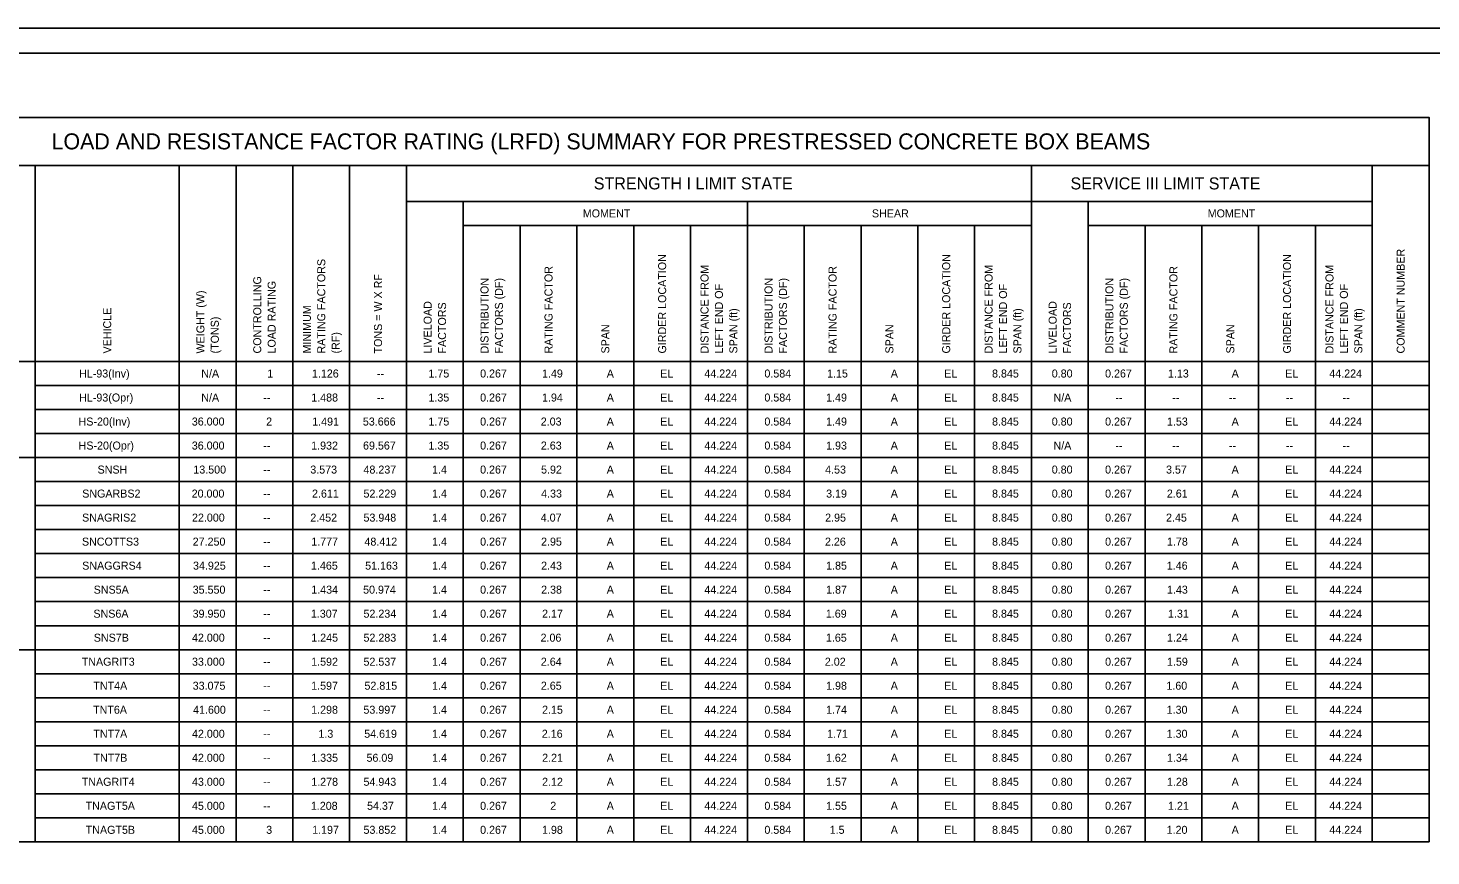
# Model space of a CAD drawing. Extents: x -169 to 381, y 285 to 620.
# Drawn here: x 28.2 to 247.3, y 375.4 to 504.7 of the extents above; entities that cross this region are included whole.
import ezdxf

# ---------------------------------------------------------------- set-up
doc = ezdxf.new("R2010")
doc.units = 0
for name, color, linetype in [('Bill of Material Border Lines', 7, 'Continuous'), ('Bill of Material Lines', 7, 'Continuous'), ('Miscellaneous Lines', 7, 'Continuous'), ('Plan Sheet CELL', 7, 'Continuous'), ('Plot Shape CELL', 7, 'Continuous'), ('Text', 7, 'Continuous')]:
    doc.layers.add(name, color=color, linetype=linetype)

msp = doc.modelspace()

# ---------------------------------------------------------------- linework, layer by layer
at = {"layer": 'Bill of Material Border Lines'}
msp.add_lwpolyline([(10.55, 490.71), (247.05, 490.71), (247.05, 377.59), (10.55, 377.59), (10.55, 490.71)], dxfattribs=at)
at = {"layer": 'Bill of Material Lines'}
for p, q in [((10.55, 483.21), (247.05, 483.21)), ((29.3, 483.21), (29.3, 377.59)), ((51.8, 483.21), (51.8, 377.59)), ((60.67, 483.21), (60.67, 377.59)), ((69.55, 483.21), (69.55, 377.59)), ((78.42, 483.21), (78.42, 377.59)), ((87.3, 483.21), (87.3, 377.59)), ((184.92, 483.21), (184.92, 377.59)), ((238.17, 483.21), (238.17, 377.59)), ((247.05, 483.21), (247.05, 377.59)), ((87.3, 477.59), (238.17, 477.59)), ((96.17, 477.59), (96.17, 377.59)), ((140.55, 477.59), (140.55, 377.59)), ((193.8, 477.59), (193.8, 377.59)), ((96.17, 473.84), (184.92, 473.84)), ((105.05, 473.84), (105.05, 377.59)), ((113.92, 473.84), (113.92, 377.59)), ((122.8, 473.84), (122.8, 377.59)), ((131.67, 473.84), (131.67, 377.59)), ((149.42, 473.84), (149.42, 377.59)), ((158.3, 473.84), (158.3, 377.59)), ((167.17, 473.84), (167.17, 377.59)), ((176.05, 473.84), (176.05, 377.59)), ((193.8, 473.84), (238.17, 473.84)), ((202.67, 473.84), (202.67, 377.59)), ((211.55, 473.84), (211.55, 377.59)), ((220.42, 473.84), (220.42, 377.59)), ((229.3, 473.84), (229.3, 377.59)), ((10.55, 452.59), (247.05, 452.59)), ((29.3, 448.84), (247.05, 448.84)), ((29.3, 445.09), (247.05, 445.09)), ((29.3, 441.34), (247.05, 441.34)), ((10.55, 437.59), (247.05, 437.59)), ((29.3, 433.84), (247.05, 433.84)), ((29.3, 430.09), (247.05, 430.09)), ((29.3, 426.34), (247.05, 426.34)), ((29.3, 422.59), (247.05, 422.59)), ((29.3, 418.84), (247.05, 418.84)), ((29.3, 415.09), (247.05, 415.09)), ((29.3, 411.34), (247.05, 411.34)), ((23.17, 407.59), (247.05, 407.59)), ((29.3, 403.84), (247.05, 403.84)), ((29.3, 400.09), (247.05, 400.09)), ((29.3, 396.34), (247.05, 396.34)), ((29.3, 392.59), (247.05, 392.59)), ((29.3, 388.84), (247.05, 388.84)), ((29.3, 385.09), (247.05, 385.09)), ((29.3, 381.34), (247.05, 381.34))]:
    msp.add_line(p, q, dxfattribs=at)
at = {"layer": 'Plan Sheet CELL'}
msp.add_line((3.77, 500.71), (323.78, 500.71), dxfattribs=at)
at = {"layer": 'Plot Shape CELL'}
msp.add_lwpolyline([(-6.77, 504.65), (323.86, 504.65), (323.86, 284.65), (-6.77, 284.65)], close=True, dxfattribs=at)

# ---------------------------------------------------------------- texts
at = {"layer": 'Miscellaneous Lines'}
for s, p in [('1', (65.54, 450.09)), ('1.13', (206.25, 450.09)), ('44.224', (231.46, 450.09)), ('2', (65.38, 442.59)), ('1.49', (152.85, 442.59)), ('8.845', (178.77, 442.59)), ('3', (65.38, 378.84)), ('1.20', (206.05, 378.84)), ('44.224', (231.46, 378.84))]:
    msp.add_text(s, height=1.25, dxfattribs=at).set_placement(p)
at = {"layer": 'Text'}
for s, height, p in [('LOAD AND RESISTANCE FACTOR RATING (LRFD) SUMMARY FOR PRESTRESSED CONCRETE BOX BEAMS', 2.5, (31.85, 485.71)), ('STRENGTH I LIMIT STATE', 1.875, (116.56, 479.46)), ('SERVICE III LIMIT STATE', 1.875, (191.03, 479.46)), ('MOMENT', 1.25, (114.84, 475.09)), ('SHEAR', 1.25, (160.01, 475.09)), ('MOMENT', 1.25, (212.46, 475.09)), ('HL-93(Inv)', 1.25, (36.15, 450.09)), ('N/A', 1.25, (55.24, 450.09)), ('1.126', 1.25, (72.53, 450.09)), ('--', 1.25, (82.67, 450.09)), ('1.75', 1.25, (90.73, 450.09)), ('0.267', 1.25, (98.8, 450.09)), ('1.49', 1.25, (108.47, 450.09)), ('A', 1.25, (118.58, 450.09)), ('EL', 1.25, (126.94, 450.09)), ('44.224', 1.25, (133.83, 450.09)), ('0.584', 1.25, (143.21, 450.09)), ('1.15', 1.25, (153, 450.09)), ('A', 1.25, (162.95, 450.09)), ('EL', 1.25, (171.31, 450.09)), ('8.845', 1.25, (178.77, 450.09)), ('0.80', 1.25, (188.1, 450.09)), ('0.267', 1.25, (196.43, 450.09)), ('A', 1.25, (216.2, 450.09)), ('EL', 1.25, (224.56, 450.09)), ('HL-93(Opr)', 1.25, (36.16, 446.34)), ('N/A', 1.25, (55.24, 446.34)), ('1.488', 1.25, (72.42, 446.34)), ('1.35', 1.25, (90.73, 446.34)), ('0.267', 1.25, (98.8, 446.34)), ('1.94', 1.25, (108.47, 446.34)), ('A', 1.25, (118.58, 446.34)), ('EL', 1.25, (126.94, 446.34)), ('44.224', 1.25, (133.83, 446.34)), ('0.584', 1.25, (143.21, 446.34)), ('1.49', 1.25, (152.85, 446.34)), ('A', 1.25, (162.95, 446.34)), ('EL', 1.25, (171.31, 446.34)), ('8.845', 1.25, (178.77, 446.34)), ('N/A', 1.25, (188.37, 446.34)), ('--', 1.25, (64.92, 446.34)), ('--', 1.25, (82.67, 446.34)), ('--', 1.25, (198.04, 446.34)), ('--', 1.25, (206.92, 446.34)), ('--', 1.25, (215.79, 446.34)), ('--', 1.25, (224.67, 446.34)), ('--', 1.25, (233.54, 446.34)), ('HS-20(Inv)', 1.25, (36.07, 442.59)), ('36.000', 1.25, (53.76, 442.59)), ('1.491', 1.25, (72.57, 442.59)), ('53.666', 1.25, (80.48, 442.59)), ('1.75', 1.25, (90.73, 442.59)), ('0.267', 1.25, (98.8, 442.59)), ('2.03', 1.25, (108.27, 442.59)), ('A', 1.25, (118.58, 442.59)), ('EL', 1.25, (126.94, 442.59)), ('44.224', 1.25, (133.83, 442.59)), ('0.584', 1.25, (143.21, 442.59)), ('A', 1.25, (162.95, 442.59)), ('EL', 1.25, (171.31, 442.59)), ('0.80', 1.25, (188.1, 442.59)), ('0.267', 1.25, (196.43, 442.59)), ('1.53', 1.25, (206.1, 442.59)), ('A', 1.25, (216.2, 442.59)), ('EL', 1.25, (224.56, 442.59)), ('44.224', 1.25, (231.46, 442.59)), ('HS-20(Opr)', 1.25, (36.08, 438.84)), ('36.000', 1.25, (53.76, 438.84)), ('--', 1.25, (64.92, 438.84)), ('1.932', 1.25, (72.41, 438.84)), ('69.567', 1.25, (80.51, 438.84)), ('1.35', 1.25, (90.73, 438.84)), ('0.267', 1.25, (98.8, 438.84)), ('2.63', 1.25, (108.29, 438.84)), ('A', 1.25, (118.58, 438.84)), ('EL', 1.25, (126.94, 438.84)), ('44.224', 1.25, (133.83, 438.84)), ('0.584', 1.25, (143.21, 438.84)), ('1.93', 1.25, (152.85, 438.84)), ('A', 1.25, (162.95, 438.84)), ('EL', 1.25, (171.31, 438.84)), ('8.845', 1.25, (178.77, 438.84)), ('N/A', 1.25, (188.37, 438.84)), ('--', 1.25, (198.04, 438.84)), ('--', 1.25, (206.92, 438.84)), ('--', 1.25, (215.79, 438.84)), ('--', 1.25, (224.67, 438.84)), ('--', 1.25, (233.54, 438.84)), ('SNSH', 1.25, (39.04, 435.09)), ('13.500', 1.25, (54, 435.09)), ('3.573', 1.25, (72.27, 435.09)), ('48.237', 1.25, (80.58, 435.09)), ('1.4', 1.25, (91.29, 435.09)), ('0.267', 1.25, (98.8, 435.09)), ('5.92', 1.25, (108.32, 435.09)), ('A', 1.25, (118.58, 435.09)), ('EL', 1.25, (126.94, 435.09)), ('44.224', 1.25, (133.83, 435.09)), ('0.584', 1.25, (143.21, 435.09)), ('4.53', 1.25, (152.7, 435.09)), ('A', 1.25, (162.95, 435.09)), ('EL', 1.25, (171.31, 435.09)), ('8.845', 1.25, (178.77, 435.09)), ('0.80', 1.25, (188.1, 435.09)), ('0.267', 1.25, (196.43, 435.09)), ('3.57', 1.25, (205.95, 435.09)), ('A', 1.25, (216.2, 435.09)), ('EL', 1.25, (224.56, 435.09)), ('44.224', 1.25, (231.46, 435.09)), ('--', 1.25, (64.92, 435.09)), ('SNGARBS2', 1.25, (36.64, 431.34)), ('20.000', 1.25, (53.74, 431.34)), ('--', 1.25, (64.92, 431.34)), ('2.611', 1.25, (72.54, 431.34)), ('52.229', 1.25, (80.58, 431.34)), ('1.4', 1.25, (91.29, 431.34)), ('0.267', 1.25, (98.8, 431.34)), ('4.33', 1.25, (108.33, 431.34)), ('A', 1.25, (118.58, 431.34)), ('EL', 1.25, (126.94, 431.34)), ('44.224', 1.25, (133.83, 431.34)), ('0.584', 1.25, (143.21, 431.34)), ('3.19', 1.25, (152.85, 431.34)), ('A', 1.25, (162.95, 431.34)), ('EL', 1.25, (171.31, 431.34)), ('8.845', 1.25, (178.77, 431.34)), ('0.80', 1.25, (188.1, 431.34)), ('0.267', 1.25, (196.43, 431.34)), ('2.61', 1.25, (206.08, 431.34)), ('A', 1.25, (216.2, 431.34)), ('EL', 1.25, (224.56, 431.34)), ('44.224', 1.25, (231.46, 431.34)), ('SNAGRIS2', 1.25, (36.62, 427.59)), ('22.000', 1.25, (53.79, 427.59)), ('--', 1.25, (64.92, 427.59)), ('2.452', 1.25, (72.27, 427.59)), ('53.948', 1.25, (80.58, 427.59)), ('1.4', 1.25, (91.29, 427.59)), ('0.267', 1.25, (98.8, 427.59)), ('4.07', 1.25, (108.27, 427.59)), ('A', 1.25, (118.58, 427.59)), ('EL', 1.25, (126.94, 427.59)), ('44.224', 1.25, (133.83, 427.59)), ('0.584', 1.25, (143.21, 427.59)), ('2.95', 1.25, (152.7, 427.59)), ('A', 1.25, (162.95, 427.59)), ('EL', 1.25, (171.31, 427.59)), ('8.845', 1.25, (178.77, 427.59)), ('0.80', 1.25, (188.1, 427.59)), ('0.267', 1.25, (196.43, 427.59)), ('2.45', 1.25, (205.95, 427.59)), ('A', 1.25, (216.2, 427.59)), ('EL', 1.25, (224.56, 427.59)), ('44.224', 1.25, (231.46, 427.59)), ('SNCOTTS3', 1.25, (36.6, 423.84)), ('27.250', 1.25, (53.9, 423.84)), ('--', 1.25, (64.92, 423.84)), ('1.777', 1.25, (72.42, 423.84)), ('48.412', 1.25, (80.73, 423.84)), ('1.4', 1.25, (91.29, 423.84)), ('0.267', 1.25, (98.8, 423.84)), ('2.95', 1.25, (108.32, 423.84)), ('A', 1.25, (118.58, 423.84)), ('EL', 1.25, (126.94, 423.84)), ('44.224', 1.25, (133.83, 423.84)), ('0.584', 1.25, (143.21, 423.84)), ('2.26', 1.25, (152.67, 423.84)), ('A', 1.25, (162.95, 423.84)), ('EL', 1.25, (171.31, 423.84)), ('8.845', 1.25, (178.77, 423.84)), ('0.80', 1.25, (188.1, 423.84)), ('0.267', 1.25, (196.43, 423.84)), ('1.78', 1.25, (206.1, 423.84)), ('A', 1.25, (216.2, 423.84)), ('EL', 1.25, (224.56, 423.84)), ('44.224', 1.25, (231.46, 423.84)), ('SNAGGRS4', 1.25, (36.64, 420.09)), ('34.925', 1.25, (53.95, 420.09)), ('1.465', 1.25, (72.38, 420.09)), ('51.163', 1.25, (80.84, 420.09)), ('1.4', 1.25, (91.29, 420.09)), ('0.267', 1.25, (98.8, 420.09)), ('2.43', 1.25, (108.33, 420.09)), ('A', 1.25, (118.58, 420.09)), ('EL', 1.25, (126.94, 420.09)), ('44.224', 1.25, (133.83, 420.09)), ('0.584', 1.25, (143.21, 420.09)), ('1.85', 1.25, (152.85, 420.09)), ('A', 1.25, (162.95, 420.09)), ('EL', 1.25, (171.31, 420.09)), ('8.845', 1.25, (178.77, 420.09)), ('0.80', 1.25, (188.1, 420.09)), ('0.267', 1.25, (196.43, 420.09)), ('1.46', 1.25, (206.07, 420.09)), ('A', 1.25, (216.2, 420.09)), ('EL', 1.25, (224.56, 420.09)), ('44.224', 1.25, (231.46, 420.09)), ('--', 1.25, (64.92, 420.09)), ('SNS5A', 1.25, (38.43, 416.34)), ('35.550', 1.25, (53.9, 416.34)), ('--', 1.25, (64.92, 416.34)), ('1.434', 1.25, (72.42, 416.34)), ('50.974', 1.25, (80.52, 416.34)), ('1.4', 1.25, (91.29, 416.34)), ('0.267', 1.25, (98.8, 416.34)), ('2.38', 1.25, (108.33, 416.34)), ('A', 1.25, (118.58, 416.34)), ('EL', 1.25, (126.94, 416.34)), ('44.224', 1.25, (133.83, 416.34)), ('0.584', 1.25, (143.21, 416.34)), ('1.87', 1.25, (152.85, 416.34)), ('A', 1.25, (162.95, 416.34)), ('EL', 1.25, (171.31, 416.34)), ('8.845', 1.25, (178.77, 416.34)), ('0.80', 1.25, (188.1, 416.34)), ('0.267', 1.25, (196.43, 416.34)), ('1.43', 1.25, (206.1, 416.34)), ('A', 1.25, (216.2, 416.34)), ('EL', 1.25, (224.56, 416.34)), ('44.224', 1.25, (231.46, 416.34)), ('SNS6A', 1.25, (38.39, 412.59)), ('39.950', 1.25, (53.89, 412.59)), ('--', 1.25, (64.92, 412.59)), ('1.307', 1.25, (72.36, 412.59)), ('52.234', 1.25, (80.58, 412.59)), ('1.4', 1.25, (91.29, 412.59)), ('0.267', 1.25, (98.8, 412.59)), ('2.17', 1.25, (108.48, 412.59)), ('A', 1.25, (118.58, 412.59)), ('EL', 1.25, (126.94, 412.59)), ('44.224', 1.25, (133.83, 412.59)), ('0.584', 1.25, (143.21, 412.59)), ('1.69', 1.25, (152.81, 412.59)), ('A', 1.25, (162.95, 412.59)), ('EL', 1.25, (171.31, 412.59)), ('8.845', 1.25, (178.77, 412.59)), ('0.80', 1.25, (188.1, 412.59)), ('0.267', 1.25, (196.43, 412.59)), ('1.31', 1.25, (206.26, 412.59)), ('A', 1.25, (216.2, 412.59)), ('EL', 1.25, (224.56, 412.59)), ('44.224', 1.25, (231.46, 412.59)), ('SNS7B', 1.25, (38.45, 408.84)), ('42.000', 1.25, (53.79, 408.84)), ('1.245', 1.25, (72.42, 408.84)), ('52.283', 1.25, (80.58, 408.84)), ('1.4', 1.25, (91.29, 408.84)), ('0.267', 1.25, (98.8, 408.84)), ('2.06', 1.25, (108.24, 408.84)), ('A', 1.25, (118.58, 408.84)), ('EL', 1.25, (126.94, 408.84)), ('44.224', 1.25, (133.83, 408.84)), ('0.584', 1.25, (143.21, 408.84)), ('1.65', 1.25, (152.82, 408.84)), ('A', 1.25, (162.95, 408.84)), ('EL', 1.25, (171.31, 408.84)), ('8.845', 1.25, (178.77, 408.84)), ('0.80', 1.25, (188.1, 408.84)), ('0.267', 1.25, (196.43, 408.84)), ('1.24', 1.25, (206.1, 408.84)), ('A', 1.25, (216.2, 408.84)), ('EL', 1.25, (224.56, 408.84)), ('44.224', 1.25, (231.46, 408.84)), ('--', 1.25, (64.92, 408.84)), ('TNAGRIT3', 1.25, (36.57, 405.09)), ('33.000', 1.25, (53.79, 405.09)), ('--', 1.25, (64.92, 405.09)), ('1.592', 1.25, (72.41, 405.09)), ('52.537', 1.25, (80.58, 405.09)), ('1.4', 1.25, (91.29, 405.09)), ('0.267', 1.25, (98.8, 405.09)), ('2.64', 1.25, (108.29, 405.09)), ('A', 1.25, (118.58, 405.09)), ('EL', 1.25, (126.94, 405.09)), ('44.224', 1.25, (133.83, 405.09)), ('0.584', 1.25, (143.21, 405.09)), ('2.02', 1.25, (152.65, 405.09)), ('A', 1.25, (162.95, 405.09)), ('EL', 1.25, (171.31, 405.09)), ('8.845', 1.25, (178.77, 405.09)), ('0.80', 1.25, (188.1, 405.09)), ('0.267', 1.25, (196.43, 405.09)), ('1.59', 1.25, (206.1, 405.09)), ('A', 1.25, (216.2, 405.09)), ('EL', 1.25, (224.56, 405.09)), ('44.224', 1.25, (231.46, 405.09)), ('TNT4A', 1.25, (38.38, 401.34)), ('33.075', 1.25, (53.9, 401.34)), ('--', 1.25, (64.92, 401.34)), ('1.597', 1.25, (72.41, 401.34)), ('52.815', 1.25, (80.73, 401.34)), ('1.4', 1.25, (91.29, 401.34)), ('0.267', 1.25, (98.8, 401.34)), ('2.65', 1.25, (108.29, 401.34)), ('A', 1.25, (118.58, 401.34)), ('EL', 1.25, (126.94, 401.34)), ('44.224', 1.25, (133.83, 401.34)), ('0.584', 1.25, (143.21, 401.34)), ('1.98', 1.25, (152.85, 401.34)), ('A', 1.25, (162.95, 401.34)), ('EL', 1.25, (171.31, 401.34)), ('8.845', 1.25, (178.77, 401.34)), ('0.80', 1.25, (188.1, 401.34)), ('0.267', 1.25, (196.43, 401.34)), ('1.60', 1.25, (206.01, 401.34)), ('A', 1.25, (216.2, 401.34)), ('EL', 1.25, (224.56, 401.34)), ('44.224', 1.25, (231.46, 401.34)), ('TNT6A', 1.25, (38.34, 397.59)), ('41.600', 1.25, (53.96, 397.59)), ('--', 1.25, (64.92, 397.59)), ('1.298', 1.25, (72.41, 397.59)), ('53.997', 1.25, (80.57, 397.59)), ('1.4', 1.25, (91.29, 397.59)), ('0.267', 1.25, (98.8, 397.59)), ('2.15', 1.25, (108.48, 397.59)), ('A', 1.25, (118.58, 397.59)), ('EL', 1.25, (126.94, 397.59)), ('44.224', 1.25, (133.83, 397.59)), ('0.584', 1.25, (143.21, 397.59)), ('1.74', 1.25, (152.85, 397.59)), ('A', 1.25, (162.95, 397.59)), ('EL', 1.25, (171.31, 397.59)), ('8.845', 1.25, (178.77, 397.59)), ('0.80', 1.25, (188.1, 397.59)), ('0.267', 1.25, (196.43, 397.59)), ('1.30', 1.25, (206.05, 397.59)), ('A', 1.25, (216.2, 397.59)), ('EL', 1.25, (224.56, 397.59)), ('44.224', 1.25, (231.46, 397.59)), ('TNT7A', 1.25, (38.38, 393.84)), ('42.000', 1.25, (53.79, 393.84)), ('1.3', 1.25, (73.54, 393.84)), ('54.619', 1.25, (80.69, 393.84)), ('1.4', 1.25, (91.29, 393.84)), ('0.267', 1.25, (98.8, 393.84)), ('2.16', 1.25, (108.44, 393.84)), ('A', 1.25, (118.58, 393.84)), ('EL', 1.25, (126.94, 393.84)), ('44.224', 1.25, (133.83, 393.84)), ('0.584', 1.25, (143.21, 393.84)), ('1.71', 1.25, (153.01, 393.84)), ('A', 1.25, (162.95, 393.84)), ('EL', 1.25, (171.31, 393.84)), ('8.845', 1.25, (178.77, 393.84)), ('0.80', 1.25, (188.1, 393.84)), ('0.267', 1.25, (196.43, 393.84)), ('1.30', 1.25, (206.05, 393.84)), ('A', 1.25, (216.2, 393.84)), ('EL', 1.25, (224.56, 393.84)), ('44.224', 1.25, (231.46, 393.84)), ('--', 1.25, (64.92, 393.84)), ('TNT7B', 1.25, (38.4, 390.09)), ('42.000', 1.25, (53.79, 390.09)), ('--', 1.25, (64.92, 390.09)), ('1.335', 1.25, (72.42, 390.09)), ('56.09', 1.25, (81.05, 390.09)), ('1.4', 1.25, (91.29, 390.09)), ('0.267', 1.25, (98.8, 390.09)), ('2.21', 1.25, (108.49, 390.09)), ('A', 1.25, (118.58, 390.09)), ('EL', 1.25, (126.94, 390.09)), ('44.224', 1.25, (133.83, 390.09)), ('0.584', 1.25, (143.21, 390.09)), ('1.62', 1.25, (152.82, 390.09)), ('A', 1.25, (162.95, 390.09)), ('EL', 1.25, (171.31, 390.09)), ('8.845', 1.25, (178.77, 390.09)), ('0.80', 1.25, (188.1, 390.09)), ('0.267', 1.25, (196.43, 390.09)), ('1.34', 1.25, (206.1, 390.09)), ('A', 1.25, (216.2, 390.09)), ('EL', 1.25, (224.56, 390.09)), ('44.224', 1.25, (231.46, 390.09)), ('TNAGRIT4', 1.25, (36.57, 386.34)), ('43.000', 1.25, (53.79, 386.34)), ('--', 1.25, (64.92, 386.34)), ('1.278', 1.25, (72.42, 386.34)), ('54.943', 1.25, (80.58, 386.34)), ('1.4', 1.25, (91.29, 386.34)), ('0.267', 1.25, (98.8, 386.34)), ('2.12', 1.25, (108.48, 386.34)), ('A', 1.25, (118.58, 386.34)), ('EL', 1.25, (126.94, 386.34)), ('44.224', 1.25, (133.83, 386.34)), ('0.584', 1.25, (143.21, 386.34)), ('1.57', 1.25, (152.85, 386.34)), ('A', 1.25, (162.95, 386.34)), ('EL', 1.25, (171.31, 386.34)), ('8.845', 1.25, (178.77, 386.34)), ('0.80', 1.25, (188.1, 386.34)), ('0.267', 1.25, (196.43, 386.34)), ('1.28', 1.25, (206.1, 386.34)), ('A', 1.25, (216.2, 386.34)), ('EL', 1.25, (224.56, 386.34)), ('44.224', 1.25, (231.46, 386.34)), ('TNAGT5A', 1.25, (37.17, 382.59)), ('45.000', 1.25, (53.79, 382.59)), ('1.208', 1.25, (72.36, 382.59)), ('54.37', 1.25, (81.14, 382.59)), ('1.4', 1.25, (91.29, 382.59)), ('0.267', 1.25, (98.8, 382.59)), ('2', 1.25, (109.76, 382.59)), ('A', 1.25, (118.58, 382.59)), ('EL', 1.25, (126.94, 382.59)), ('44.224', 1.25, (133.83, 382.59)), ('0.584', 1.25, (143.21, 382.59)), ('1.55', 1.25, (152.85, 382.59)), ('A', 1.25, (162.95, 382.59)), ('EL', 1.25, (171.31, 382.59)), ('8.845', 1.25, (178.77, 382.59)), ('0.80', 1.25, (188.1, 382.59)), ('0.267', 1.25, (196.43, 382.59)), ('1.21', 1.25, (206.26, 382.59)), ('A', 1.25, (216.2, 382.59)), ('EL', 1.25, (224.56, 382.59)), ('44.224', 1.25, (231.46, 382.59)), ('--', 1.25, (64.92, 382.59)), ('TNAGT5B', 1.25, (37.19, 378.84)), ('45.000', 1.25, (53.79, 378.84)), ('1.197', 1.25, (72.56, 378.84)), ('53.852', 1.25, (80.58, 378.84)), ('1.4', 1.25, (91.29, 378.84)), ('0.267', 1.25, (98.8, 378.84)), ('1.98', 1.25, (108.47, 378.84)), ('A', 1.25, (118.58, 378.84)), ('EL', 1.25, (126.94, 378.84)), ('44.224', 1.25, (133.83, 378.84)), ('0.584', 1.25, (143.21, 378.84)), ('1.5', 1.25, (153.41, 378.84)), ('A', 1.25, (162.95, 378.84)), ('EL', 1.25, (171.31, 378.84)), ('8.845', 1.25, (178.77, 378.84)), ('0.80', 1.25, (188.1, 378.84)), ('0.267', 1.25, (196.43, 378.84)), ('A', 1.25, (216.2, 378.84)), ('EL', 1.25, (224.56, 378.84))]:
    msp.add_text(s, height=height, dxfattribs=at).set_placement(p)
for s, p in [('GIRDER LOCATION', (127.86, 453.84)), ('GIRDER LOCATION', (172.23, 453.84)), ('GIRDER LOCATION', (225.48, 453.84)), ('COMMENT NUMBER', (243.23, 453.84)), ('RATING FACTORS', (74.61, 453.84)), ('RATING FACTOR ', (110.11, 453.84)), ('DISTANCE FROM', (134.48, 453.84)), ('RATING FACTOR ', (154.48, 453.84)), ('DISTANCE FROM', (178.86, 453.84)), ('RATING FACTOR', (207.73, 453.84)), ('DISTANCE FROM', (232.11, 453.84)), ('CONTROLLING ', (64.61, 453.84)), ('LOAD RATING ', (66.86, 453.84)), ('TONS = W X RF ', (83.48, 453.84)), ('DISTRIBUTION', (100.11, 453.84)), ('FACTORS (DF)', (102.36, 453.84)), ('LEFT END OF', (136.73, 453.84)), ('DISTRIBUTION', (144.48, 453.84)), ('FACTORS (DF)', (146.73, 453.84)), ('LEFT END OF', (181.11, 453.84)), ('DISTRIBUTION', (197.73, 453.84)), ('FACTORS (DF)', (199.98, 453.84)), ('LEFT END OF', (234.36, 453.84)), ('WEIGHT (W) ', (55.73, 453.84)), ('VEHICLE', (41.17, 453.84)), ('MINIMUM', (72.36, 453.84)), ('LIVELOAD', (91.23, 453.84)), ('FACTORS ', (93.48, 453.84)), ('SPAN (ft)', (138.98, 453.84)), ('SPAN (ft)', (183.36, 453.84)), ('LIVELOAD', (188.86, 453.84)), ('FACTORS ', (191.11, 453.84)), ('SPAN (ft)', (236.61, 453.84)), ('(TONS) ', (57.98, 453.84)), ('SPAN', (118.98, 453.84)), ('SPAN ', (163.36, 453.84)), ('SPAN', (216.61, 453.84)), ('(RF)', (76.86, 453.84))]:
    msp.add_text(s, height=1.25, rotation=90, dxfattribs=at).set_placement(p)

doc.saveas('drawing.dxf')
